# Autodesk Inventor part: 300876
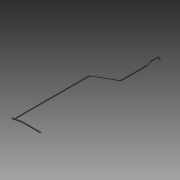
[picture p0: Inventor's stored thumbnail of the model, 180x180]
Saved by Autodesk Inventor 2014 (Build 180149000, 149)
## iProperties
Created: 2007-12
Part Number: 300876
Document SubType Name: Modeling
Designer: MM
Density: 8.08 g/cm^3
Mass: 81.1085 g
Surface Area: 92.7417 cm^2
Volume: 10.0382 cm^3
Material: Stainless Steel
Description: LEFT SIDE WIRE BAR
Appearance: Dark Gray
Component Category: Back Component
Author: MM
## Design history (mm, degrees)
node "300677" dims "d0" = 10
workaxis "Work Axis1"
workplane "Work Plane1"
workplane "Work Plane2"
body "Solid1"
tag "TaggingFeature2"
feature "DerivedBody::D-300677" dims "d0" = 10
other parameters: "d1" = 90 deg, "d2" = 0
